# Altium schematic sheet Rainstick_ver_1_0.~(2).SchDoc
size A4
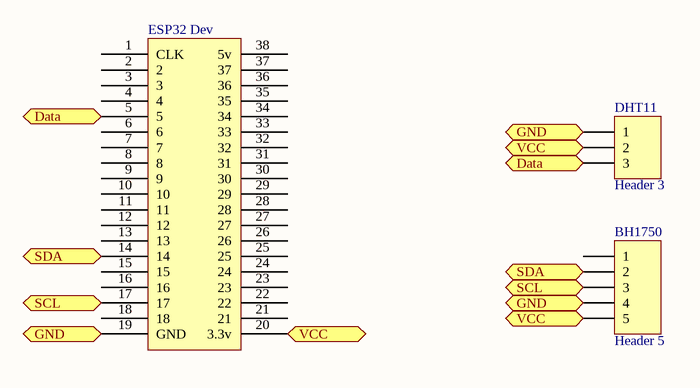
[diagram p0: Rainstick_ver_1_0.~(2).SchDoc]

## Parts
BH1750  Header 5  [HDR1X5]
DHT11  Header 3  [HDR1X3]
ESP32_Dev  (no value)  [PCBComponent_1]

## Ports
Data, GND, SCL, SDA, VCC

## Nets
Data: DHT11.3 ESP32_Dev.5 ; port Data
GND: BH1750.4 DHT11.1 ESP32_Dev.19(GND) ; port GND
SCL: BH1750.3 ESP32_Dev.17 ; port SCL
SDA: BH1750.2 ESP32_Dev.14 ; port SDA
VCC: BH1750.5 DHT11.2 ESP32_Dev.20(3.3v) ; port VCC

Not connected (* = marked no-connect by the designer): BH1750 1; ESP32_Dev 1(CLK) 2 3 4 6 7 8 9 10 11 12 13 15 16 18 21 22 23 24 25 26 27 28 29 30 31 32 33 34 35 36 37 38(5v)

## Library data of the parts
BH1750 = Header 5: Header, 5-Pin
DHT11 = Header 3: Header, 3-Pin
ESP32_Dev = Component_1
